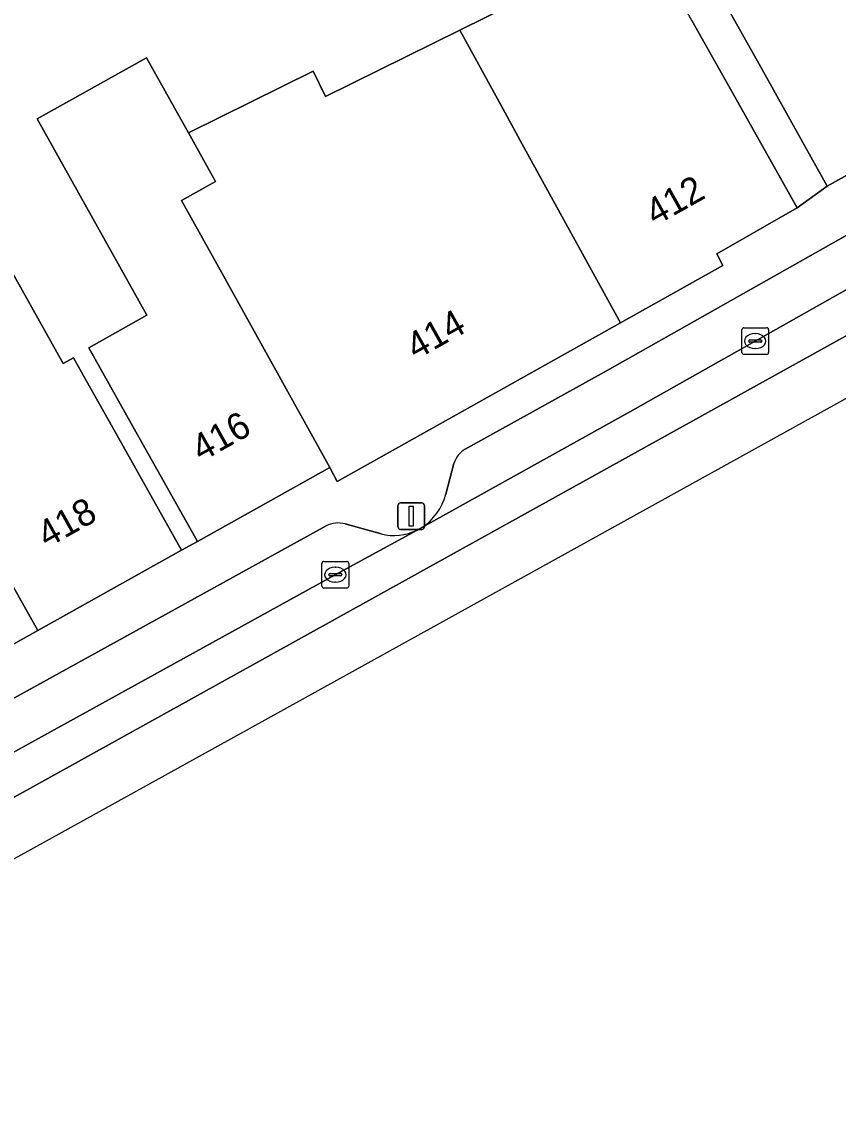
# Model space of a CAD drawing. Extents: x 159217 to 160349, y 381246 to 382172.
# Drawn here: x 159842.55 to 159873.14, y 381427.21 to 381468.35 of the extents above; entities that cross this region are included whole.
import ezdxf

# ---------------------------------------------------------------- set-up
doc = ezdxf.new("R2010")
doc.units = 0
for name, color, linetype in [('IMGEO_Erf', 7, 'Continuous'), ('IMGEO_Kolk', 7, 'Continuous'), ('IMGEO_Lichtmast', 7, 'Continuous'), ('IMGEO_Pand', 7, 'Continuous'), ('IMGEO_Pand_nummerreeks', 7, 'Continuous'), ('IMGEO_Parkeervlak_open', 7, 'Continuous'), ('IMGEO_Rijbaan_lokaal_gesloten', 7, 'Continuous'), ('IMGEO_Voetpad_open', 7, 'Continuous')]:
    doc.layers.add(name, color=color, linetype=linetype)

msp = doc.modelspace()

# ---------------------------------------------------------------- linework, layer by layer
at = {"layer": 'IMGEO_Erf'}
for points in [[(159867.654, 381468.413), (159869.153, 381465.741), (159871.6, 381461.381), (159872.727, 381462.201), (159870.286, 381466.565), (159866.496, 381473.34)], [(159841.604, 381459.989), (159844.1, 381455.542), (159844.485, 381455.758), (159844.963, 381454.907), (159846.058, 381452.956), (159848.535, 381448.542), (159849.129, 381448.874), (159846.651, 381453.291), (159845.06, 381456.136), (159847.237, 381457.361), (159843.123, 381464.717), (159847.22, 381467.008), (159848.795, 381464.192), (159853.466, 381466.505), (159853.934, 381465.56), (159858.962, 381468.051), (159865.923, 381471.499)]]:
    msp.add_lwpolyline(points, dxfattribs=at)
at = {"layer": 'IMGEO_Kolk'}
for p, q in [((159869.532, 381455.959), (159869.532, 381456.811)), ((159869.607, 381456.885), (159870.459, 381456.885)), ((159870.02, 381456.665), (159870.045, 381456.665)), ((159870.533, 381456.811), (159870.533, 381455.959)), ((159869.791, 381456.379), (159869.791, 381456.391)), ((159870.229, 381456.342), (159869.831, 381456.342)), ((159869.834, 381456.428), (159870.232, 381456.428)), ((159870.043, 381456.105), (159870.018, 381456.105)), ((159870.275, 381456.391), (159870.275, 381456.379)), ((159870.459, 381455.885), (159869.607, 381455.885)), ((159853.797, 381447.198), (159853.797, 381448.05)), ((159853.872, 381448.124), (159854.724, 381448.124)), ((159854.285, 381447.904), (159854.31, 381447.904)), ((159854.798, 381448.05), (159854.798, 381447.198)), ((159854.056, 381447.618), (159854.056, 381447.63)), ((159854.494, 381447.581), (159854.096, 381447.581)), ((159854.099, 381447.667), (159854.497, 381447.667)), ((159854.54, 381447.63), (159854.54, 381447.618)), ((159854.724, 381447.124), (159853.872, 381447.124)), ((159854.308, 381447.344), (159854.283, 381447.344))]:
    msp.add_line(p, q, dxfattribs=at)
for points in [[(159869.532, 381455.959), (159869.532, 381456.811)], [(159869.607, 381456.885), (159870.459, 381456.885)], [(159870.533, 381456.811), (159870.533, 381455.959)], [(159870.459, 381455.885), (159869.607, 381455.885)], [(159853.797, 381447.198), (159853.797, 381448.05)], [(159853.872, 381448.124), (159854.724, 381448.124)], [(159854.798, 381448.05), (159854.798, 381447.198)], [(159854.724, 381447.124), (159853.872, 381447.124)]]:
    msp.add_lwpolyline(points, dxfattribs=at)
for centre, radius, start, end in [((159869.609, 381456.809), 0.0765, 91.552, 178.448), ((159869.609, 381456.809), 0.0765, 91.552, 178.448), ((159870.457, 381456.809), 0.0765, 1.552, 88.448), ((159870.457, 381456.809), 0.0765, 1.552, 88.448), ((159869.831, 381456.388), 0.0403, 85.8775, 175.7526), ((159869.828, 381456.378), 0.0366, 178.938, 274.7102), ((159870.232, 381456.385), 0.043, 264.8664, 352.4533), ((159870.236, 381456.39), 0.0386, 1.7309, 96.639), ((159869.609, 381455.961), 0.0765, 181.552, 268.448), ((159869.609, 381455.961), 0.0765, 181.552, 268.448), ((159870.457, 381455.961), 0.0765, 271.552, 358.448), ((159870.457, 381455.961), 0.0765, 271.552, 358.448), ((159853.874, 381448.048), 0.0765, 91.552, 178.448), ((159853.874, 381448.048), 0.0765, 91.552, 178.448), ((159854.722, 381448.048), 0.0765, 1.552, 88.448), ((159854.722, 381448.048), 0.0765, 1.552, 88.448), ((159854.096, 381447.627), 0.0403, 85.8775, 175.7526), ((159854.093, 381447.617), 0.0366, 178.938, 274.7102), ((159854.497, 381447.624), 0.043, 264.8664, 352.4533), ((159854.501, 381447.629), 0.0386, 1.7309, 96.639), ((159853.874, 381447.2), 0.0765, 181.552, 268.448), ((159853.874, 381447.2), 0.0765, 181.552, 268.448), ((159854.722, 381447.2), 0.0765, 271.552, 358.448), ((159854.722, 381447.2), 0.0765, 271.552, 358.448)]:
    msp.add_arc(centre, radius, start, end, dxfattribs=at)
for centre, major_axis, ratio, start_param, end_param in [((159870.019, 381456.385), (-0.387, 0.002), 0.722429, 4.712389, 7.853982), ((159870.044, 381456.385), (-0.39, 0.002), 0.717154, 1.570796, 4.712389), ((159854.284, 381447.624), (-0.387, 0.002), 0.722429, 4.712389, 7.853982), ((159854.309, 381447.624), (-0.39, 0.002), 0.717154, 1.570796, 4.712389)]:
    msp.add_ellipse(centre, major_axis=major_axis, ratio=ratio, start_param=start_param, end_param=end_param, dxfattribs=at)
at = {"layer": 'IMGEO_Lichtmast'}
for p, q in [((159856.645, 381449.421), (159856.645, 381450.221)), ((159856.645, 381450.221), (159856.645, 381449.421)), ((159856.745, 381450.321), (159857.535, 381450.321)), ((159857.535, 381450.321), (159856.745, 381450.321)), ((159857.635, 381450.221), (159857.635, 381449.421)), ((159857.635, 381449.421), (159857.635, 381450.221)), ((159857.535, 381449.321), (159856.745, 381449.321)), ((159856.745, 381449.321), (159857.535, 381449.321))]:
    msp.add_line(p, q, dxfattribs=at)
msp.add_lwpolyline([(159857.065, 381450.196), (159857.215, 381450.196), (159857.215, 381449.446), (159857.065, 381449.446), (159857.065, 381450.196)], dxfattribs=at)
for centre, start, end in [((159856.745, 381450.221), 90, 180), ((159856.745, 381450.221), 90, 180), ((159857.535, 381450.221), 0, 90), ((159857.535, 381450.221), 360, 90), ((159856.745, 381449.421), 180, 270), ((159856.745, 381449.421), 180, 270), ((159857.535, 381449.421), 270, 0), ((159857.535, 381449.421), 270, 0)]:
    msp.add_arc(centre, 0.1, start, end, dxfattribs=at)
at = {"layer": 'IMGEO_Pand'}
for points in [[(159866.496, 381473.34), (159870.286, 381466.565), (159872.727, 381462.201), (159881.132, 381466.89), (159880.919, 381467.271), (159878.468, 381471.652), (159875.276, 381477.358), (159873.723, 381480.135), (159868.46, 381477.79), (159866.431, 381476.885), (159867.786, 381473.931), (159867.484, 381473.793)], [(159869.153, 381465.741), (159867.654, 381468.413), (159865.923, 381471.499), (159858.962, 381468.051), (159860.661, 381464.949), (159861.304, 381463.776), (159864.978, 381457.068), (159868.814, 381459.218), (159868.589, 381459.66), (159871.6, 381461.381)], [(159860.661, 381464.949), (159858.962, 381468.051), (159853.934, 381465.56), (159853.466, 381466.505), (159848.795, 381464.192), (159849.812, 381462.373), (159849.721, 381462.322), (159848.527, 381461.654), (159850.045, 381458.941), (159850.369, 381458.359), (159854.096, 381451.65), (159854.366, 381451.122), (159864.978, 381457.068), (159861.304, 381463.776)], [(159848.795, 381464.192), (159847.22, 381467.008), (159843.123, 381464.717), (159847.237, 381457.361), (159845.06, 381456.136), (159846.651, 381453.291), (159849.129, 381448.874), (159854.096, 381451.65), (159850.369, 381458.359), (159850.045, 381458.941), (159848.527, 381461.654), (159849.721, 381462.322), (159849.812, 381462.373)], [(159833.421, 381463.793), (159834.299, 381462.228), (159837.004, 381457.408), (159836.601, 381457.182), (159843.148, 381445.532), (159848.535, 381448.542), (159846.058, 381452.956), (159844.963, 381454.907), (159844.485, 381455.758), (159844.1, 381455.542), (159841.604, 381459.989), (159839.595, 381458.862), (159837.089, 381463.329), (159836.889, 381463.684), (159836.062, 381465.268)], [(159836.601, 381457.182), (159834.092, 381455.774), (159836.537, 381451.418), (159833.686, 381449.818), (159833.844, 381449.534), (159837.763, 381442.522), (159843.148, 381445.532)]]:
    msp.add_lwpolyline(points, close=True, dxfattribs=at)
at = {"layer": 'IMGEO_Parkeervlak_open'}
for points in [[(159857.536, 381449.393), (159865.335, 381453.733), (159870.029, 381456.383), (159876.597, 381460.101), (159882.803, 381463.671)], [(159879.329, 381463.698), (159875.852, 381461.707), (159864.486, 381455.289), (159859.167, 381452.337)], [(159858.74, 381451.798), (159858.435, 381450.641)], [(159856.01, 381449.152), (159854.665, 381449.53)], [(159822.941, 381430.317), (159854.294, 381447.623), (159857.362, 381449.298)], [(159853.95, 381449.457), (159833.702, 381438.282)]]:
    msp.add_lwpolyline(points, dxfattribs=at)
for centre, radius, start, end in [((159859.677, 381451.494), 0.985, 121.194, 162.0329), ((159856.373, 381451.178), 2.131, 303.0756, 345.39), ((159854.401, 381448.58), 0.986, 74.4574, 117.2018), ((159856.482, 381451.119), 2.022, 256.5184, 295.8084)]:
    msp.add_arc(centre, radius, start, end, dxfattribs=at)
at = {"layer": 'IMGEO_Rijbaan_lokaal_gesloten'}
msp.add_lwpolyline([(159824.612, 381427.213), (159931.265, 381486.272), (159986.055, 381517.88), (159986.055, 381517.88), (159985.577, 381518.699), (159980.645, 381515.791), (159956.076, 381502.58), (159939.951, 381494.362), (159923.443, 381485.375), (159911.619, 381478.616), (159897.952, 381470.628), (159877.989, 381459.107), (159830.923, 381432.992), (159823.666, 381428.97), (159824.612, 381427.213)], close=True, dxfattribs=at)
msp.add_lwpolyline([(159876.597, 381460.101), (159870.029, 381456.383), (159865.335, 381453.733), (159857.536, 381449.393), (159857.362, 381449.298), (159854.294, 381447.623), (159822.941, 381430.317), (159823.666, 381428.97), (159830.923, 381432.992), (159877.989, 381459.107)], dxfattribs=at)
at = {"layer": 'IMGEO_Voetpad_open'}
for points in [[(159881.132, 381466.89), (159872.727, 381462.201), (159871.6, 381461.381), (159868.589, 381459.66), (159868.814, 381459.218), (159864.978, 381457.068), (159854.366, 381451.122), (159854.096, 381451.65), (159849.129, 381448.874), (159848.535, 381448.542), (159843.148, 381445.532), (159837.763, 381442.522), (159832.608, 381439.641), (159827.374, 381436.716), (159818.776, 381431.911), (159816.767, 381430.781)], [(159859.167, 381452.337), (159864.486, 381455.289), (159875.852, 381461.707), (159879.329, 381463.698)], [(159858.435, 381450.641), (159858.74, 381451.798)], [(159854.665, 381449.53), (159856.01, 381449.152)], [(159833.702, 381438.282), (159853.95, 381449.457)], [(159857.362, 381449.298), (159857.536, 381449.393)]]:
    msp.add_lwpolyline(points, dxfattribs=at)
for centre, radius, start, end in [((159859.677, 381451.494), 0.985, 121.194, 162.0329), ((159856.373, 381451.178), 2.131, 303.0756, 345.39), ((159854.401, 381448.58), 0.986, 74.4574, 117.2018), ((159856.482, 381451.119), 2.022, 256.5184, 295.8084)]:
    msp.add_arc(centre, radius, start, end, dxfattribs=at)

# ---------------------------------------------------------------- texts
at = {"layer": 'IMGEO_Pand_nummerreeks'}
for s, rotation, p in [('412', 29.2667, (159866.281, 381460.688)), ('414', 29.2667, (159857.316, 381455.664)), ('416', 29.1979, (159849.269, 381451.839)), ('418', 29.1979, (159843.492, 381448.61))]:
    msp.add_text(s, height=1, rotation=rotation, dxfattribs=at).set_placement(p)

doc.saveas('drawing.dxf')
